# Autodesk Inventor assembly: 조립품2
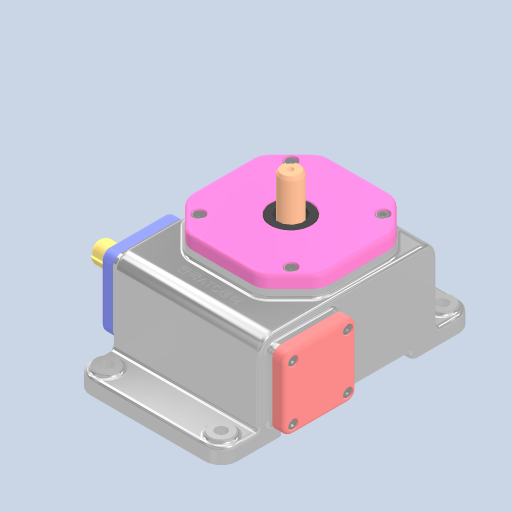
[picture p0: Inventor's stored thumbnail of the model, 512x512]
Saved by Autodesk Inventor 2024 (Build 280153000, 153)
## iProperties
Created: 2026-02
Part Number: 조립품2
Document SubType Name: Assembly
Designer: 2-10
Author: 2-10
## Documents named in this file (14)
- C:\Users\2-10\Desktop\760203V1005\답안조립품.iam
- C:\Users\2-10\Desktop\760203V1005\본체.ipt
- C:\Users\2-10\Desktop\760203V1005\6각 구멍붙이 볼트 M4x10.ipt
- C:\Users\2-10\Desktop\760203V1005\6각 구멍붙이 볼트 M5x10.ipt
- C:\Users\2-10\Desktop\760203V1005\뒷커버.ipt
- C:\Users\2-10\Desktop\760203V1005\앞커버.ipt
- C:\Users\2-10\Desktop\760203V1005\오일 실 17 32 8.ipt
- C:\Users\2-10\Desktop\760203V1005\웜 샤프트.ipt
- C:\Users\2-10\Desktop\760203V1005\웜 휠 커버.ipt
- C:\Users\2-10\Desktop\760203V1005\웜 휠.ipt
- C:\Users\2-10\Desktop\760203V1005\축.ipt
- C:\Users\2-10\Desktop\760203V1005\칼라.ipt
- C:\Users\2-10\Desktop\760203V1005\테이퍼 롤러 베어링 30203.ipt
- C:\Users\2-10\Desktop\760203V1005\평행 키 5x5x16.ipt
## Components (12 placed, 2 different names)
1. 6각 구멍붙이 볼트 M4x10:1
2. 6각 구멍붙이 볼트 M5x10:1
3. 6각 구멍붙이 볼트 M4x10:2
4. 6각 구멍붙이 볼트 M4x10:3
5. 6각 구멍붙이 볼트 M4x10:4
6. 6각 구멍붙이 볼트 M4x10:5
7. 6각 구멍붙이 볼트 M4x10:6
8. 6각 구멍붙이 볼트 M4x10:7
9. 6각 구멍붙이 볼트 M4x10:8
10. 6각 구멍붙이 볼트 M5x10:2
11. 6각 구멍붙이 볼트 M5x10:3
12. 6각 구멍붙이 볼트 M5x10:4
